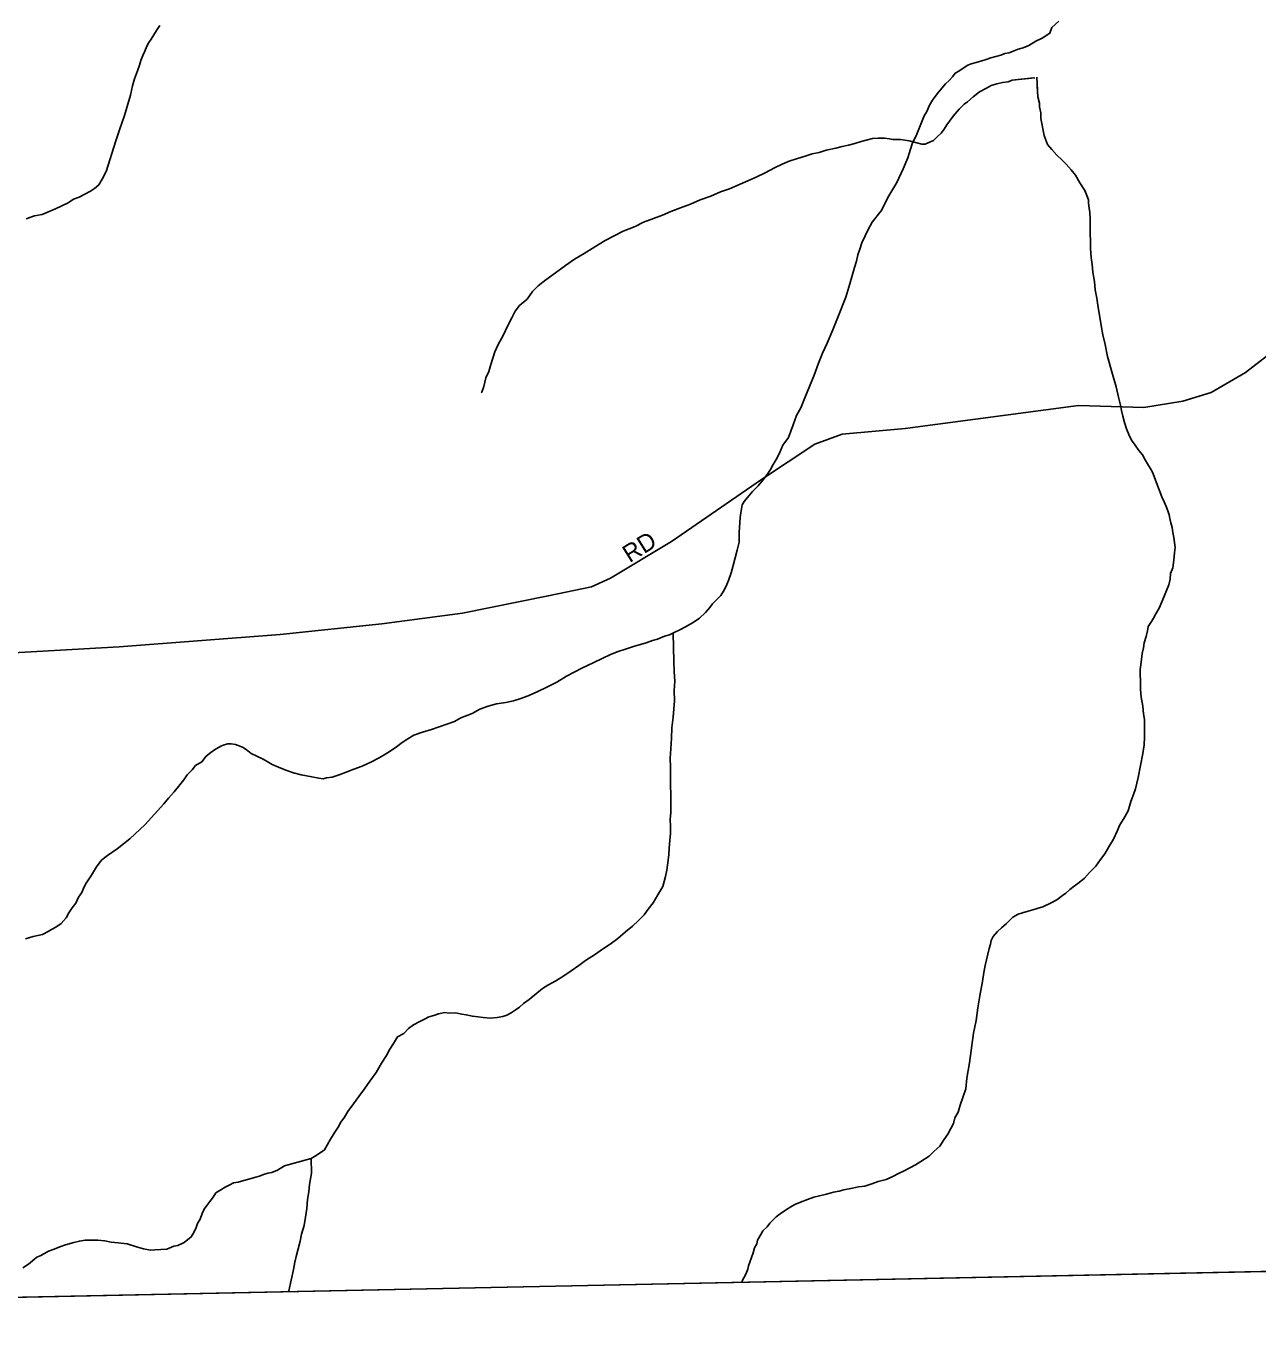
# Model space of a CAD drawing. Extents: x 2010165 to 2382125, y 1060529 to 1407316.
# Drawn here: x 2219461 to 2222969, y 1195199 to 1198951 of the extents above; entities that cross this region are included whole.
import ezdxf

# ---------------------------------------------------------------- set-up
doc = ezdxf.new("R2010")
doc.units = 0
for name, color, linetype in [('GM_X_Adjacent_County', 7, 'Continuous'), ('GM_X_City_Street', 7, 'Continuous'), ('GM_X_City_Street_Text', 7, 'Continuous'), ('GM_X_Corporation', 7, 'Continuous'), ('GM_X_County', 7, 'Continuous'), ('GM_X_Minor_River', 7, 'Continuous')]:
    doc.layers.add(name, color=color, linetype=linetype)

msp = doc.modelspace()

# ---------------------------------------------------------------- linework, layer by layer
at = {"layer": 'GM_X_Adjacent_County'}
msp.add_lwpolyline([(2218436, 1195308), (2224284, 1195428.9)], dxfattribs=at)
at = {"layer": 'GM_X_City_Street'}
msp.add_lwpolyline([(2218819.8, 1197131.1), (2219725.7, 1197182.9), (2220183.7, 1197217.8), (2220473.7, 1197248.4), (2220703.6, 1197278.9), (2220947.6, 1197327.5), (2221071.5, 1197353.8), (2221125.5, 1197378), (2221299.4, 1197482.6), (2221555.2, 1197659.5), (2221707.1, 1197760.1), (2221785.1, 1197788.3), (2221965, 1197804.7), (2222458.5, 1197870.7), (2222644.4, 1197864.9), (2222756, 1197882.5), (2222836.2, 1197907.9), (2222934.1, 1197964.7), (2223030, 1198039), (2223123.9, 1198113.4), (2223186.5, 1198138.9)], dxfattribs=at)
at = {"layer": 'GM_X_Corporation'}
msp.add_lwpolyline([(2225489.9, 1195453.9), (2213202.5, 1195199)], dxfattribs=at)
at = {"layer": 'GM_X_County'}
msp.add_lwpolyline([(2224284, 1195428.9), (2218436, 1195308)], dxfattribs=at)
at = {"layer": 'GM_X_Minor_River'}
for points in [[(2219841.6, 1198953.3), (2219831.8, 1198939.1), (2219823.9, 1198927), (2219816.1, 1198914.8), (2219810.2, 1198904.7), (2219804.3, 1198894.6), (2219798.5, 1198880.4), (2219792.6, 1198868.3), (2219786.8, 1198854.2), (2219783, 1198840.1), (2219777.2, 1198824), (2219769.4, 1198801.8), (2219763.7, 1198781.6), (2219758, 1198755.4), (2219750.4, 1198729.2), (2219740.8, 1198697), (2219727.2, 1198658.7), (2219715.7, 1198624.4), (2219688.7, 1198537.7), (2219677, 1198515.5), (2219667.2, 1198499.3), (2219655.3, 1198489.1), (2219643.4, 1198480.9), (2219611.5, 1198464.4), (2219595.6, 1198458.2), (2219579.7, 1198448), (2219543.8, 1198431.4), (2219525.9, 1198423.2), (2219506, 1198414.9), (2219484, 1198410.6), (2219460.1, 1198402.3)], [(2222402.1, 1198965.9), (2222382.3, 1198947.5), (2222376.5, 1198931.4), (2222354.6, 1198917.1), (2222336.7, 1198908.8), (2222316.8, 1198896.5), (2222300.9, 1198890.3), (2222286.9, 1198886.1), (2222277, 1198881.9), (2222261, 1198875.7), (2222249, 1198873.5), (2222237.1, 1198869.4), (2222223.1, 1198865.2), (2222209.1, 1198861), (2222195.1, 1198856.8), (2222183.2, 1198852.6), (2222167.2, 1198848.4), (2222153.2, 1198844.2), (2222143.3, 1198840.1), (2222127.4, 1198829.8), (2222117.4, 1198823.7)], [(2222117.4, 1198823.7), (2222107.5, 1198817.5), (2222099.6, 1198807.4), (2222089.7, 1198797.2), (2222079.8, 1198787.1), (2222064, 1198768.8), (2222056.2, 1198758.6), (2222042.4, 1198740.4), (2222034.5, 1198726.2), (2222026.8, 1198708.1), (2222018.9, 1198695.9), (2221995.6, 1198639.4), (2221985.8, 1198619.2), (2221980.1, 1198601.1), (2221972.4, 1198576.8), (2221958.8, 1198544.6), (2221941.2, 1198506.2), (2221917.7, 1198467.7), (2221896.2, 1198425.3), (2221870.6, 1198392.8), (2221858.8, 1198370.6), (2221851, 1198354.4), (2221841.3, 1198334.2), (2221835.5, 1198316.1), (2221829.7, 1198299.9), (2221825.9, 1198281.8), (2221820.2, 1198263.7), (2221814.4, 1198243.5), (2221806.7, 1198217.3), (2221795.2, 1198179), (2221773.9, 1198124.5), (2221758.4, 1198086.2), (2221742.8, 1198047.8), (2221729.2, 1198019.6), (2221717.5, 1197991.3), (2221705.9, 1197957), (2221692.3, 1197924.7), (2221678.7, 1197892.4), (2221667.1, 1197864.1), (2221655.3, 1197841.9), (2221645.7, 1197815.7), (2221632.1, 1197779.4), (2221616.4, 1197757.1), (2221606.6, 1197734.9), (2221596.9, 1197716.7), (2221589, 1197702.5), (2221581.2, 1197688.4), (2221571.4, 1197674.2), (2221559.6, 1197658), (2221545.7, 1197641.7), (2221529.9, 1197625.5), (2221514.1, 1197607.2), (2221506.2, 1197597), (2221500.4, 1197586.9), (2221496.7, 1197564.8), (2221494.8, 1197550.7), (2221491.4, 1197508.5), (2221491.7, 1197480.4), (2221486, 1197458.2), (2221480.3, 1197436.1), (2221474.6, 1197413.9), (2221468.8, 1197393.8), (2221461.1, 1197371.6), (2221453.3, 1197353.4), (2221447.5, 1197341.3), (2221439.6, 1197329.1), (2221429.7, 1197319), (2221415.9, 1197304.7), (2221408, 1197294.6), (2221396.2, 1197280.4), (2221378.3, 1197264.1), (2221360.5, 1197251.8), (2221338.6, 1197239.5), (2221322.7, 1197231.3), (2221306.7, 1197223), (2221292.8, 1197216.8), (2221278.8, 1197212.6), (2221258.9, 1197204.3), (2221244.9, 1197200.1), (2221227, 1197193.9), (2221191, 1197183.4), (2221171.1, 1197177.1), (2221147.2, 1197168.8), (2221125.2, 1197160.5), (2221077.4, 1197137.8), (2221043.6, 1197121.3), (2220999.8, 1197098.6), (2220972, 1197082.2), (2220944.1, 1197067.8), (2220918.2, 1197055.4), (2220890.3, 1197043), (2220866.4, 1197034.7), (2220848.4, 1197028.4), (2220826.5, 1197024.1), (2220800.5, 1197019.8), (2220776.5, 1197013.4), (2220752.6, 1197005.1), (2220730.7, 1196992.8), (2220698.8, 1196980.3), (2220680.9, 1196970.1), (2220615.1, 1196947.1)], [(2222334.1, 1198804.3), (2222270, 1198797.5), (2222330.1, 1198804.3), (2222270, 1198797.5), (2222258.1, 1198793.3), (2222242.1, 1198791.1), (2222226.1, 1198786.9), (2222210.1, 1198782.7), (2222196.2, 1198774.5), (2222176.3, 1198764.2), (2222158.5, 1198749.9), (2222142.6, 1198735.6), (2222132.7, 1198729.5), (2222118.8, 1198715.3), (2222101.1, 1198695), (2222091.2, 1198680.8), (2222083.4, 1198670.6), (2222075.5, 1198658.5), (2222067.6, 1198646.3), (2222055.8, 1198636.1), (2222045.9, 1198626), (2222031.9, 1198619.8), (2222022, 1198615.6), (2222011.9, 1198615.5), (2221997.9, 1198619.3), (2221975.8, 1198625.1), (2221951.7, 1198628.8), (2221929.6, 1198628.5), (2221919.6, 1198630.4), (2221905.5, 1198632.2), (2221887.5, 1198632), (2221871.5, 1198631.8), (2221857.5, 1198627.6), (2221839.5, 1198623.3), (2221821.6, 1198617.1), (2221803.6, 1198612.8), (2221785.6, 1198608.6), (2221767.6, 1198604.4), (2221739.7, 1198598), (2221719.7, 1198591.7), (2221699.7, 1198587.4), (2221679.8, 1198581.1), (2221657.8, 1198574.8), (2221633.9, 1198566.5), (2221614, 1198558.2), (2221592.1, 1198547.9), (2221566.2, 1198533.5), (2221540.3, 1198521.1), (2221464.6, 1198488.1), (2221438.7, 1198479.7), (2221410.8, 1198467.3), (2221380.9, 1198456.9), (2221353, 1198444.5), (2221325, 1198434.1), (2221297.1, 1198423.7), (2221273.2, 1198413.3), (2221247.3, 1198403), (2221219.4, 1198392.6), (2221195.5, 1198380.2), (2221161.6, 1198367.7), (2221137.7, 1198355.4), (2221109.9, 1198341), (2221080.1, 1198322.5), (2221050.2, 1198304.1), (2221022.4, 1198287.6), (2220996.6, 1198269.2), (2220968.8, 1198248.8), (2220941, 1198228.4), (2220919.2, 1198212), (2220903.4, 1198195.8), (2220887.6, 1198173.5), (2220865.8, 1198155.1), (2220854, 1198138.9), (2220844.2, 1198120.7), (2220832.5, 1198098.5), (2220818.9, 1198070.2), (2220805.2, 1198043.9), (2220795.4, 1198023.7), (2220789.6, 1198005.6), (2220783.9, 1197987.4), (2220778.1, 1197967.3), (2220770.3, 1197949.1), (2220764.6, 1197924.9), (2220758.8, 1197908.8), (2220756.9, 1197906.8)], [(2222340.1, 1198806.4), (2222342.8, 1198750.2), (2222340.4, 1198780.3), (2222342.8, 1198750.2), (2222347, 1198732.2), (2222347.2, 1198722.2), (2222351.4, 1198704.2), (2222351.6, 1198688.1), (2222360.3, 1198640), (2222364.4, 1198630), (2222370.6, 1198614.1), (2222382.8, 1198600.2), (2222397, 1198584.3), (2222411.3, 1198570.4), (2222423.4, 1198558.5), (2222437.7, 1198542.6), (2222449.9, 1198526.7), (2222462.2, 1198504.8), (2222476.5, 1198482.9), (2222482.7, 1198468.9), (2222486.9, 1198456.9), (2222487, 1198446.9), (2222489.2, 1198432.8), (2222491.3, 1198420.8), (2222491.6, 1198402.8), (2222491.8, 1198382.7), (2222492.1, 1198360.6), (2222492.4, 1198338.5), (2222492.7, 1198318.4), (2222495, 1198292.4), (2222497.3, 1198272.3), (2222499.6, 1198250.3), (2222503.9, 1198224.2), (2222506.2, 1198200.1), (2222510.6, 1198176.1), (2222514.9, 1198150.1), (2222519.3, 1198122), (2222523.6, 1198098), (2222527.9, 1198071.9), (2222534.3, 1198043.9), (2222540.8, 1198009.8), (2222555.4, 1197959.8), (2222565.9, 1197923.8), (2222572.3, 1197893.8), (2222578.6, 1197871.8), (2222580.8, 1197855.7), (2222585.1, 1197839.7), (2222589.3, 1197821.7), (2222595.5, 1197803.7), (2222601.8, 1197787.7), (2222610, 1197771.8), (2222620.2, 1197757.8), (2222630.4, 1197741.9), (2222640.6, 1197730), (2222648.8, 1197716), (2222655, 1197704.1), (2222663.1, 1197692.1), (2222669.3, 1197680.1), (2222688, 1197630.2), (2222696.2, 1197610.2), (2222702.4, 1197596.2), (2222708.6, 1197582.3), (2222712.8, 1197570.3), (2222717, 1197558.3), (2222719.1, 1197548.2), (2222721.3, 1197536.2), (2222725.4, 1197522.2), (2222727.6, 1197508.2), (2222729.8, 1197494.2), (2222732, 1197480.1), (2222734.2, 1197466.1), (2222732.4, 1197450), (2222730.6, 1197429.9), (2222726.9, 1197407.8), (2222721.1, 1197391.7), (2222719.3, 1197375.6), (2222715.5, 1197359.5), (2222709.7, 1197343.3), (2222703.9, 1197329.2), (2222696.1, 1197311), (2222688.4, 1197292.8), (2222678.5, 1197276.7), (2222672.7, 1197264.5), (2222666.8, 1197254.4), (2222657, 1197240.2), (2222655.1, 1197228.2), (2222651.3, 1197212.1), (2222645.6, 1197193.9), (2222643.7, 1197179.8), (2222639.9, 1197163.7), (2222638.1, 1197147.6), (2222636.3, 1197131.5), (2222634.5, 1197117.5), (2222634.7, 1197103.4), (2222634.9, 1197085.3), (2222635.3, 1197061.2), (2222637.5, 1197039.2), (2222641.9, 1197013.1), (2222644.2, 1196991.1), (2222646.4, 1196975.1), (2222646.6, 1196959)], [(2221304, 1197221.8), (2221305.8, 1197140.7), (2221306.2, 1197112.6), (2221308.5, 1197084.5), (2221306.9, 1197058.4), (2221307.3, 1197028.2), (2221305.6, 1197006.1), (2221303.9, 1196982), (2221300.2, 1196951.9), (2221298.6, 1196921.7), (2221297, 1196891.6), (2221295.4, 1196865.4), (2221295.7, 1196839.3), (2221296, 1196815.3), (2221296.4, 1196789.2), (2221296.7, 1196761.1), (2221297, 1196737), (2221297.4, 1196708.9), (2221295.6, 1196690.8), (2221295.9, 1196670.7), (2221296.1, 1196650.6), (2221294.4, 1196630.5), (2221292.7, 1196608.4), (2221290.9, 1196590.3), (2221289.1, 1196574.2), (2221287.3, 1196560.1), (2221285.5, 1196546.1), (2221281.7, 1196527.9), (2221274.1, 1196499.7), (2221260.4, 1196475.5), (2221246.6, 1196453.2), (2221232.8, 1196434.9), (2221221, 1196418.7), (2221205.2, 1196402.5), (2221187.4, 1196386.2), (2221167.6, 1196369.9), (2221145.8, 1196351.5), (2221123.9, 1196335.2), (2221102.1, 1196320.8), (2221082.2, 1196306.5), (2221054.4, 1196288.1), (2221034.6, 1196273.8), (2221012.7, 1196259.4), (2220988.9, 1196243.1), (2220969, 1196230.8), (2220947.1, 1196218.4), (2220931.2, 1196208.2), (2220893.6, 1196177.6), (2220877.7, 1196165.4), (2220865.8, 1196155.2), (2220853.9, 1196147), (2220842, 1196138.8), (2220830, 1196132.6), (2220818.1, 1196128.4), (2220802.1, 1196126.2), (2220782.1, 1196124), (2220762, 1196125.7), (2220747.9, 1196127.6), (2220731.9, 1196129.4), (2220713.8, 1196133.1), (2220701.8, 1196135), (2220683.7, 1196138.8), (2220665.6, 1196138.6), (2220653.6, 1196140.4), (2220635.6, 1196136.2), (2220621.7, 1196132), (2220607.7, 1196127.8), (2220595.7, 1196121.6), (2220579.8, 1196113.4), (2220563.9, 1196105.1), (2220550, 1196094.9), (2220536.2, 1196080.7), (2220518.3, 1196070.4), (2220506.5, 1196052.2), (2220496.7, 1196036), (2220486.9, 1196017.8), (2220473.2, 1195995.5), (2220457.5, 1195969.2), (2220439.8, 1195944.9), (2220424, 1195922.6), (2220408.3, 1195900.3), (2220392.5, 1195880.1), (2220376.8, 1195857.8), (2220367, 1195841.6), (2220357.1, 1195827.4), (2220349.3, 1195813.2), (2220339.5, 1195799.1), (2220327.7, 1195778.8), (2220310.1, 1195748.5), (2220286.2, 1195732.1), (2220272.3, 1195723.9), (2220272.9, 1195681.8), (2220267.3, 1195649.6), (2220265.5, 1195629.4), (2220261.8, 1195607.3), (2220260.2, 1195581.2), (2220256.5, 1195557.1), (2220252.8, 1195532.9), (2220245.1, 1195508.7), (2220241.3, 1195488.6), (2220235.6, 1195466.4)], [(2222646.6, 1196959), (2222646.8, 1196942.9), (2222647, 1196924.9), (2222645.3, 1196902.8), (2222641.6, 1196878.6), (2222628.5, 1196810.2), (2222624.7, 1196794.1), (2222620.9, 1196777.9), (2222615.1, 1196761.8), (2222607.4, 1196741.6), (2222599.7, 1196715.4), (2222587.9, 1196693.2), (2222576.2, 1196675), (2222568.4, 1196656.8), (2222558.7, 1196634.6), (2222544.9, 1196612.3), (2222533.2, 1196592.1), (2222521.3, 1196575.9), (2222507.6, 1196557.6), (2222489.8, 1196539.3), (2222476, 1196523.1), (2222460.1, 1196510.8), (2222446.2, 1196500.6), (2222434.3, 1196490.4), (2222422.4, 1196480.2), (2222412.5, 1196474.1), (2222396.6, 1196461.8), (2222378.7, 1196451.6), (2222356.8, 1196441.2), (2222340.8, 1196437), (2222328.9, 1196432.9), (2222314.9, 1196428.7), (2222298.9, 1196424.4), (2222286.9, 1196420.3), (2222271, 1196412), (2222253.2, 1196393.7), (2222239.4, 1196381.5), (2222227.5, 1196371.3), (2222215.6, 1196357.1), (2222209.8, 1196345), (2222207.9, 1196334.9), (2222204.1, 1196322.8), (2222200.3, 1196306.7), (2222196.5, 1196290.6), (2222192.7, 1196274.5), (2222188.9, 1196254.4), (2222185.2, 1196228.2), (2222177.8, 1196188), (2222172.2, 1196153.8), (2222166.7, 1196117.5), (2222159.1, 1196081.3), (2222148.2, 1195996.8), (2222144.5, 1195974.7), (2222140.7, 1195952.6), (2222137.1, 1195922.4), (2222129.4, 1195898.2), (2222121.7, 1195876), (2222116, 1195855.9), (2222106.1, 1195839.7), (2222102.3, 1195823.6), (2222094.5, 1195809.4), (2222086.7, 1195793.2), (2222074.9, 1195777), (2222063.1, 1195758.8), (2222047.3, 1195744.5), (2222033.4, 1195730.3), (2222009.6, 1195715.9), (2221993.7, 1195705.7), (2221977.8, 1195697.5), (2221961.8, 1195689.2), (2221945.9, 1195681), (2221930, 1195672.8), (2221910.1, 1195664.5), (2221888.1, 1195658.2), (2221870.2, 1195651.9), (2221850.2, 1195645.6), (2221832.2, 1195643.4), (2221814.2, 1195639.2), (2221790.2, 1195634.8), (2221776.3, 1195630.6), (2221760.3, 1195628.4), (2221740.3, 1195622.1), (2221720.3, 1195617.9), (2221704.4, 1195613.7), (2221686.4, 1195607.4), (2221666.5, 1195599.1), (2221650.5, 1195592.9), (2221638.6, 1195586.7), (2221626.7, 1195578.5), (2221608.8, 1195566.3), (2221596.9, 1195558.1), (2221579.1, 1195539.8), (2221571.2, 1195529.6), (2221559.3, 1195517.4), (2221553.5, 1195507.3), (2221543.7, 1195491.1), (2221541.8, 1195481.1), (2221535.9, 1195468.9), (2221532.1, 1195454.8), (2221522.4, 1195428.6), (2221518.5, 1195418.5)], [(2220615.1, 1196947.1), (2220589.1, 1196938.8), (2220565.2, 1196930.4), (2220547.3, 1196920.2), (2220531.4, 1196909.9), (2220515.5, 1196897.7), (2220497.7, 1196885.4), (2220477.8, 1196873.1), (2220463.9, 1196864.9), (2220444, 1196854.6), (2220418.1, 1196842.2), (2220394.1, 1196833.9), (2220372.2, 1196825.6), (2220352.3, 1196817.3), (2220332.3, 1196811), (2220316.3, 1196808.8), (2220306.3, 1196806.7), (2220294.3, 1196808.5), (2220274.2, 1196812.3), (2220244.1, 1196817.9), (2220222, 1196823.6), (2220199.8, 1196831.4), (2220179.7, 1196839.2), (2220161.5, 1196847), (2220151.5, 1196852.9), (2220135.3, 1196862.7), (2220117.2, 1196870.5), (2220101, 1196878.3), (2220086.8, 1196890.2), (2220076.7, 1196896.1), (2220056.6, 1196903.9), (2220044.6, 1196905.7), (2220034.6, 1196905.6), (2220024.6, 1196903.5), (2220014.6, 1196899.3), (2219996.7, 1196889.1), (2219986.8, 1196880.9), (2219972.9, 1196870.7), (2219961.1, 1196854.5), (2219943.2, 1196844.2), (2219933.3, 1196832), (2219919.5, 1196817.8), (2219909.6, 1196803.6), (2219897.8, 1196789.4), (2219882, 1196769.1), (2219866.3, 1196750.8), (2219852.4, 1196734.6), (2219799.1, 1196675.7), (2219755.6, 1196635), (2219719.9, 1196606.4), (2219692, 1196588), (2219676.2, 1196575.7), (2219668.3, 1196565.6), (2219660.4, 1196555.4), (2219652.6, 1196541.3), (2219644.7, 1196529.1), (2219631, 1196508.9), (2219625.1, 1196496.8), (2219619.3, 1196482.6), (2219609.5, 1196468.5), (2219601.6, 1196452.3), (2219591.8, 1196438.1), (2219582, 1196423.9), (2219574.1, 1196409.8), (2219560.3, 1196393.5), (2219544.4, 1196383.3), (2219532.5, 1196377.1), (2219522.6, 1196371), (2219506.6, 1196362.7), (2219480.7, 1196356.4), (2219458.7, 1196350.1)], [(2220272.3, 1195723.9), (2220196.5, 1195702.9), (2220176.6, 1195690.6), (2220160.6, 1195684.3), (2220148.6, 1195682.2), (2220136.7, 1195678), (2220124.7, 1195673.8), (2220110.7, 1195669.6), (2220094.8, 1195665.4), (2220080.8, 1195661.2), (2220064.8, 1195657), (2220050.8, 1195654.8), (2220040.9, 1195648.7), (2220026.9, 1195642.5), (2220015, 1195634.3), (2220001.1, 1195626.1), (2219993.2, 1195613.9), (2219983.4, 1195601.8), (2219975.5, 1195589.6), (2219967.6, 1195579.5), (2219961.8, 1195567.3), (2219956, 1195551.2), (2219948.1, 1195539.1), (2219944.3, 1195527), (2219938.5, 1195512.8), (2219930.6, 1195500.7), (2219910.8, 1195484.4), (2219892.8, 1195476.1), (2219880.9, 1195473.9), (2219860.9, 1195465.7), (2219826.9, 1195463.2), (2219814.9, 1195463.1), (2219794.8, 1195466.8), (2219774.7, 1195472.6), (2219748.5, 1195480.3), (2219722.4, 1195484), (2219702.4, 1195485.7), (2219684.3, 1195489.5), (2219664.2, 1195491.3), (2219644.2, 1195491), (2219628.2, 1195490.8), (2219612.2, 1195488.6), (2219596.2, 1195484.4), (2219572.2, 1195478), (2219556.3, 1195471.8), (2219540.3, 1195465.6), (2219524.4, 1195459.4), (2219512.5, 1195453.2), (2219500.5, 1195447), (2219490.6, 1195442.9), (2219466.8, 1195422.5), (2219450.9, 1195412.2)], [(2220235.6, 1195466.4), (2220229.9, 1195444.3), (2220226.1, 1195428.1), (2220222.3, 1195408), (2220209.1, 1195347)], [(2221518.5, 1195418.5), (2221516.7, 1195408.5), (2221510.8, 1195394.3), (2221499.8, 1195373.7)]]:
    msp.add_lwpolyline(points, dxfattribs=at)

# ---------------------------------------------------------------- texts
at = {"layer": 'GM_X_City_Street_Text'}
msp.add_text('RD', height=50, rotation=32.0029, dxfattribs=at).set_placement((2221179.6, 1197420.8))

doc.saveas('drawing.dxf')
